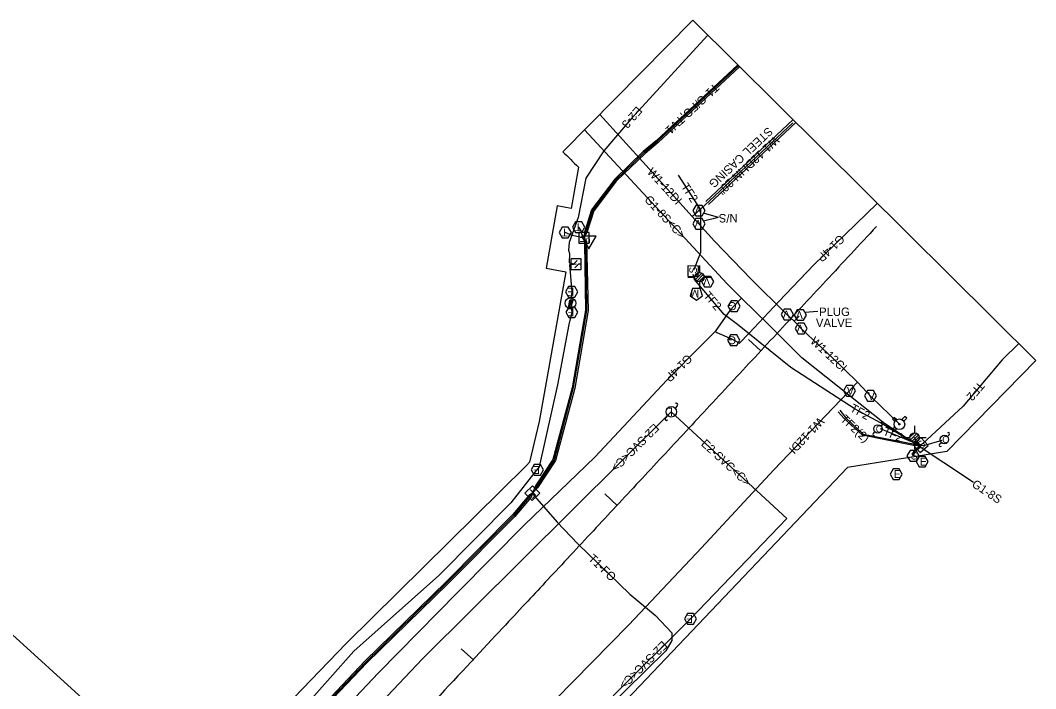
# Model space of a CAD drawing. Extents: x 1991878 to 2008544, y 770238 to 1141211.
# Drawn here: x 2008062.6 to 2008543.9, y 1139565.6 to 1139882.4 of the extents above; entities that cross this region are included whole.
import ezdxf

# ---------------------------------------------------------------- set-up
doc = ezdxf.new("R2010")
doc.units = 0
for name, color, linetype in [('RD_EX_SU_Elec', 7, 'Continuous'), ('RD_EX_SU_Gas', 7, 'Continuous'), ('RD_EX_SU_H2O', 7, 'Continuous'), ('RD_EX_SU_Misc', 7, 'Continuous'), ('RD_EX_SU_Pole', 7, 'Continuous'), ('RD_EX_SU_SwpLmt', 7, 'Continuous'), ('RD_EX_SU_Telecom', 7, 'Continuous'), ('RD_EX_SU_Trfc', 7, 'Continuous'), ('RD_EX_SU_TX_Elec', 7, 'Continuous'), ('RD_EX_SU_TX_Gas', 7, 'Continuous'), ('RD_EX_SU_TX_H2O', 7, 'Continuous'), ('RD_EX_SU_TX_Telecom', 7, 'Continuous'), ('RD_EX_SU_TX_Trfc', 7, 'Continuous'), ('RD_HC_Cl', 7, 'Continuous')]:
    doc.layers.add(name, color=color, linetype=linetype)

msp = doc.modelspace()

# ---------------------------------------------------------------- linework, layer by layer
at = {"layer": 'RD_EX_SU_Elec'}
for points in [[(2008388.37, 1139875.24), (2008352.25, 1139835.77), (2008339.19, 1139820.6), (2008330.64, 1139807.57), (2008327.03, 1139789.02), (2008322.82, 1139777.14), (2008322.44, 1139773.5), (2008322.92, 1139771.93), (2008322.8, 1139767.45), (2008326.05, 1139766.84), (2008322.91, 1139766.44), (2008324, 1139753.73), (2008323.4, 1139748.33), (2008324.09, 1139744.01), (2008322.62, 1139738.22), (2008317.2, 1139709.57), (2008308.6, 1139670.8), (2008306.52, 1139668.26), (2008295.15, 1139653.67), (2008261.07, 1139619.29), (2008220.69, 1139583.46), (2008187.13, 1139545.5)], [(2008323.55, 1139766.84), (2008324.89, 1139766.84), (2008326.58, 1139768.52)], [(2008328.55, 1139766.84), (2008327.22, 1139766.84), (2008325.53, 1139765.15)], [(2008343.6, 1139562.26), (2008380.32, 1139598.68), (2008425.97, 1139646.35), (2008371.23, 1139696.87), (2008253.32, 1139579.8), (2008186.59, 1139509.23), (2008114.35, 1139431), (2008055.21, 1139358.58), (2007994.21, 1139276.04), (2007935.15, 1139188.81), (2007828.1, 1139009.37), (2007792.89, 1138934.82)]]:
    msp.add_lwpolyline(points, dxfattribs=at)
for points in [[(2008328.55, 1139769.33), (2008323.55, 1139769.33), (2008323.55, 1139764.34), (2008328.55, 1139764.34)], [(2008321.12, 1139753.73), (2008322.56, 1139751.23), (2008325.45, 1139751.23), (2008326.89, 1139753.73), (2008325.45, 1139756.23), (2008322.56, 1139756.23)], [(2008321.21, 1139744.01), (2008322.65, 1139741.51), (2008325.54, 1139741.51), (2008326.98, 1139744.01), (2008325.54, 1139746.51), (2008322.65, 1139746.51)], [(2008324.78, 1139750.39), (2008323.78, 1139746.94), (2008323.28, 1139748.81), (2008322.51, 1139745.98), (2008323.2, 1139749.89), (2008323.76, 1139747.95)], [(2008493.04, 1139673.22), (2008491.59, 1139675.72), (2008488.71, 1139675.72), (2008487.26, 1139673.22), (2008488.71, 1139670.72), (2008491.59, 1139670.72)], [(2008304.82, 1139669.29), (2008306.27, 1139666.79), (2008309.15, 1139666.79), (2008310.6, 1139669.29), (2008309.15, 1139671.79), (2008306.27, 1139671.79)], [(2008480.67, 1139667.33), (2008479.23, 1139669.83), (2008476.34, 1139669.83), (2008474.9, 1139667.33), (2008476.34, 1139664.83), (2008479.23, 1139664.83)], [(2008377.44, 1139598.68), (2008378.88, 1139596.18), (2008381.77, 1139596.18), (2008383.21, 1139598.68), (2008381.77, 1139601.18), (2008378.88, 1139601.18)]]:
    msp.add_lwpolyline(points, close=True, dxfattribs=at)
msp.add_circle((2008323.4, 1139748.33), 2.55, dxfattribs=at)
at = {"layer": 'RD_EX_SU_Gas'}
for points in [[(2008397.47, 1139757.64), (2008351.82, 1139807.01), (2008330.11, 1139830.48)], [(2008392.07, 1139735.01), (2008392.85, 1139734.47), (2008399.7, 1139731.43), (2008403.52, 1139729.38), (2008407.96, 1139734.03), (2008422.17, 1139749.08), (2008438.65, 1139766.33), (2008468.86, 1139795.64)], [(2008514.51, 1139663.35), (2008472.32, 1139691.37), (2008433.03, 1139722.41), (2008417.25, 1139738.18), (2008404.63, 1139750.62), (2008397.47, 1139757.64)], [(2008404.55, 1139750.7), (2008403.44, 1139749.58), (2008398.9, 1139744.83), (2008391.94, 1139734.83), (2008385.92, 1139728.82), (2008369.04, 1139711.9), (2008334.96, 1139675.4), (2008301.61, 1139643.32), (2008270.11, 1139611.37), (2008232.47, 1139573.05), (2008197.32, 1139535.98), (2008163.44, 1139498.28), (2008127.84, 1139456.99), (2008097.18, 1139422.1), (2008075.86, 1139397.4), (2008030.23, 1139340.85), (2007999.81, 1139301.13), (2007969.65, 1139260.73)]]:
    msp.add_lwpolyline(points, dxfattribs=at)
for points in [[(2008399.53, 1139749.43), (2008398.08, 1139746.93), (2008399.53, 1139744.43), (2008402.41, 1139744.43), (2008403.86, 1139746.93), (2008402.41, 1139749.43)], [(2008399.32, 1139733.26), (2008397.88, 1139730.76), (2008399.32, 1139728.26), (2008402.21, 1139728.26), (2008403.65, 1139730.76), (2008402.21, 1139733.26)]]:
    msp.add_lwpolyline(points, close=True, dxfattribs=at)
at = {"layer": 'RD_EX_SU_H2O'}
for p, q in [((2008387.52, 1139796.54), (2008428.89, 1139835.31)), ((2008388.89, 1139795.08), (2008430.31, 1139833.9)), ((2008476.87, 1139694.22), (2008476, 1139693.31)), ((2008476, 1139693.31), (2008477.16, 1139692.2)), ((2008478.05, 1139693.09), (2008476.87, 1139694.22)), ((2008481.88, 1139694.63), (2008480.48, 1139693.16)), ((2008481.42, 1139692.33), (2008482.79, 1139693.76)), ((2008482.79, 1139693.76), (2008481.88, 1139694.63)), ((2008477.14, 1139689.67), (2008475.79, 1139688.25)), ((2008475.79, 1139688.25), (2008476.7, 1139687.38)), ((2008476.7, 1139687.38), (2008478.02, 1139688.77))]:
    msp.add_line(p, q, dxfattribs=at)
for points in [[(2008337.32, 1139837.77), (2008359.09, 1139813.73), (2008381.12, 1139789.42), (2008391.73, 1139777.78), (2008409.08, 1139759.67), (2008425.74, 1139743.36), (2008429.49, 1139739.79), (2008433.69, 1139735.42), (2008447.28, 1139722.79), (2008459.45, 1139710.87)], [(2008428.85, 1139833.88), (2008389.35, 1139796.85), (2008381.53, 1139789.75), (2008381.14, 1139789.39)], [(2008429.51, 1139739.77), (2008429.85, 1139740.13), (2008431.9, 1139742.18)], [(2008019.12, 1139221.08), (2008048.48, 1139262.65), (2008073.58, 1139294.58), (2008079.22, 1139302.23), (2008110.71, 1139341.71), (2008143.34, 1139380.24), (2008168.92, 1139408.5), (2008210.81, 1139454.91), (2008245.96, 1139491.17), (2008281.21, 1139525.55), (2008316.14, 1139560.25), (2008351.07, 1139595.92), (2008385.58, 1139632.4), (2008419.77, 1139669.26), (2008455.08, 1139706.22), (2008458.85, 1139710.23), (2008459.45, 1139710.87)], [(2008459.45, 1139710.87), (2008466.13, 1139703.84), (2008478.9, 1139691.52), (2008479.33, 1139690.92)]]:
    msp.add_lwpolyline(points, dxfattribs=at)
for points in [[(2008381.47, 1139792.2), (2008382.92, 1139789.7), (2008385.8, 1139789.7), (2008387.25, 1139792.2), (2008385.8, 1139794.7), (2008382.92, 1139794.7)], [(2008381.47, 1139785.9), (2008382.92, 1139783.4), (2008385.8, 1139783.4), (2008387.25, 1139785.9), (2008385.8, 1139788.4), (2008382.92, 1139788.4)], [(2008385.56, 1139758.55), (2008387.01, 1139756.05), (2008389.89, 1139756.05), (2008391.34, 1139758.55), (2008389.89, 1139761.05), (2008387.01, 1139761.05)], [(2008383.09, 1139749.73), (2008386, 1139751.84), (2008384.89, 1139755.25), (2008381.3, 1139755.25), (2008380.19, 1139751.84)], [(2008423.33, 1139742.93), (2008424.77, 1139740.43), (2008427.66, 1139740.43), (2008429.1, 1139742.93), (2008427.66, 1139745.43), (2008424.77, 1139745.43)], [(2008429.49, 1139742.71), (2008430.93, 1139740.21), (2008433.82, 1139740.21), (2008435.26, 1139742.71), (2008433.82, 1139745.21), (2008430.93, 1139745.21)], [(2008429.86, 1139736.31), (2008431.3, 1139733.81), (2008434.19, 1139733.81), (2008435.63, 1139736.31), (2008434.19, 1139738.81), (2008431.3, 1139738.81)], [(2008458.54, 1139706.79), (2008457.1, 1139709.29), (2008454.21, 1139709.29), (2008452.77, 1139706.79), (2008454.21, 1139704.29), (2008457.1, 1139704.29)], [(2008468.53, 1139704.37), (2008467.09, 1139706.87), (2008464.2, 1139706.87), (2008462.76, 1139704.37), (2008464.2, 1139701.87), (2008467.09, 1139701.87)]]:
    msp.add_lwpolyline(points, close=True, dxfattribs=at)
for radius in [2.52, 0.315]:
    msp.add_circle((2008479.33, 1139690.92), radius, dxfattribs=at)
for start, end in [(120.5537, 149.521), (33.9932, 62.9695), (209.6469, 238.6232)]:
    msp.add_arc((2008479.33, 1139690.92), 2.52, start, end, dxfattribs=at)
at = {"layer": 'RD_EX_SU_Misc'}
msp.add_lwpolyline([(2008332.18, 1139774.11), (2008335.65, 1139780.11), (2008328.72, 1139780.11)], close=True, dxfattribs=at)
at = {"layer": 'RD_EX_SU_Pole'}
for p, q in [((2008384.59, 1139766.12), (2008384.59, 1139762.83)), ((2008379.06, 1139760.61), (2008382.37, 1139760.61)), ((2008382.37, 1139760.75), (2008384.45, 1139762.83)), ((2008382.62, 1139759.58), (2008385.62, 1139762.58)), ((2008383.28, 1139758.83), (2008386.38, 1139761.92)), ((2008384.29, 1139758.42), (2008386.78, 1139760.91)), ((2008386.8, 1139760.62), (2008390.11, 1139760.62)), ((2008384.59, 1139758.4), (2008384.59, 1139755.12)), ((2008374.06, 1139699.7), (2008373, 1139698.64)), ((2008369.47, 1139695.11), (2008368.41, 1139694.04)), ((2008486.55, 1139690.12), (2008486.55, 1139686.84)), ((2008481.03, 1139684.61), (2008484.34, 1139684.62)), ((2008484.34, 1139684.75), (2008486.42, 1139686.83)), ((2008484.59, 1139683.59), (2008487.59, 1139686.58)), ((2008485.25, 1139682.83), (2008488.34, 1139685.93)), ((2008486.26, 1139682.42), (2008488.75, 1139684.92)), ((2008488.77, 1139684.62), (2008492.08, 1139684.63)), ((2008486.55, 1139682.4), (2008486.55, 1139679.12))]:
    msp.add_line(p, q, dxfattribs=at)
for centre, radius in [((2008384.59, 1139760.62), 2.22), ((2008371.23, 1139696.87), 2.5), ((2008486.55, 1139684.62), 2.22)]:
    msp.add_circle(centre, radius, dxfattribs=at)
for centre, start, end in [((2008373.53, 1139700.23), 315, 135), ((2008368.94, 1139693.51), 135, 315)]:
    msp.add_arc(centre, 0.75, start, end, dxfattribs=at)
at = {"layer": 'RD_EX_SU_SwpLmt'}
for p, q in [((2008381.44, 1139882.41), (2008319.85, 1139820.11)), ((2008381.44, 1139882.41), (2008543.95, 1139721.11)), ((2008327.21, 1139812.76), (2008323.75, 1139793.27)), ((2008321.23, 1139763.24), (2008308.62, 1139692.22)), ((2008543.95, 1139721.11), (2008501.79, 1139678.03))]:
    msp.add_line(p, q, dxfattribs=at)
for points in [[(2008323.75, 1139793.27), (2008317.17, 1139794.43), (2008311.92, 1139764.9), (2008321.23, 1139763.24)], [(2008308.62, 1139692.22), (2008303.98, 1139673.05), (2008302.61, 1139671.39), (2008217.14, 1139586.99), (2008146.65, 1139513.91), (2008110.85, 1139472.17), (2008058.97, 1139410.99), (2008013.6, 1139356.01), (2007982.19, 1139312.98), (2007954.73, 1139272.11), (2007894.74, 1139182.48), (2007866.63, 1139138.23), (2007843.93, 1139094.78), (2007785.35, 1138986.79)], [(2008501.79, 1139678.03), (2008454.81, 1139670.38), (2008273.17, 1139479.53)]]:
    msp.add_lwpolyline(points, dxfattribs=at)
msp.add_arc((2022509.04, 1154031.15), 20082, 225.044092, 225.073753, dxfattribs=at)
at = {"layer": 'RD_EX_SU_Telecom'}
for points in [[(2008403.08, 1139860.82), (2008364.54, 1139824.89), (2008358.29, 1139819.76), (2008344.82, 1139806.68), (2008333.88, 1139792.27), (2008330.57, 1139781.92), (2008329.82, 1139779.33), (2008330.66, 1139775.7), (2008331.1, 1139744.9), (2008324.72, 1139708.32), (2008315.66, 1139674.01), (2008307.42, 1139661.37), (2008305.4, 1139658.27)], [(2008402.66, 1139861.19), (2008364.05, 1139825.29), (2008357.91, 1139820.18), (2008344.46, 1139807.16), (2008333.36, 1139792.52), (2008330, 1139782.02), (2008329.82, 1139779.33)], [(2008403.49, 1139860.33), (2008364.93, 1139824.55), (2008358.82, 1139819.34), (2008345.16, 1139806.09), (2008334.42, 1139792.1), (2008331.21, 1139781.85), (2008329.82, 1139779.33)], [(2008329.82, 1139779.33), (2008328.05, 1139779.7), (2008324.26, 1139780.46), (2008320.96, 1139781.85)], [(2008329.82, 1139779.33), (2008328.95, 1139780.8), (2008328.38, 1139782.96), (2008327.32, 1139784.36)], [(2008329.82, 1139779.33), (2008330, 1139776.71), (2008330.54, 1139745.03), (2008324.17, 1139708.28), (2008315.14, 1139674.26), (2008306.86, 1139661.74), (2008305.4, 1139658.27)], [(2008329.82, 1139779.33), (2008331.06, 1139777.44), (2008331.79, 1139744.88), (2008325.48, 1139708.06), (2008316.32, 1139673.77), (2008307.85, 1139660.86), (2008305.4, 1139658.27)], [(2008305.4, 1139658.27), (2008303.69, 1139657.15), (2008296.15, 1139648.2), (2008264.57, 1139616.22), (2008225.94, 1139578.68), (2008191.19, 1139541.83), (2008155.65, 1139504.96), (2008121.25, 1139463.29), (2008090.5, 1139429.06), (2008067.62, 1139404.3), (2008020.3, 1139350.24), (2008000.26, 1139321.01), (2007991.22, 1139306.98), (2007963.62, 1139266.78), (2007931.75, 1139219.86)], [(2008305.4, 1139658.27), (2008304.18, 1139656.84), (2008296.58, 1139647.74), (2008264.95, 1139615.87), (2008226.45, 1139578.22), (2008191.55, 1139541.46), (2008156.07, 1139504.61), (2008121.74, 1139462.81), (2008090.98, 1139428.65), (2008068.11, 1139403.96), (2008020.75, 1139349.83), (2008000.71, 1139320.77), (2007991.64, 1139306.71), (2007964.15, 1139266.38), (2007932.21, 1139219.57)], [(2008305.4, 1139658.27), (2008304.81, 1139656.42), (2008297.07, 1139647.18), (2008265.35, 1139615.32), (2008226.85, 1139577.83), (2008191.88, 1139541.09), (2008156.34, 1139504.22), (2008122.19, 1139462.43), (2008091.39, 1139428.14), (2008068.51, 1139403.49), (2008021.17, 1139349.41), (2008001.14, 1139320.51), (2007992.13, 1139306.45), (2007964.8, 1139266.15), (2007932.81, 1139219.12)], [(2008305.4, 1139658.27), (2008306.31, 1139656.83), (2008317.12, 1139644.5), (2008326.86, 1139634.24), (2008351.55, 1139610.4), (2008363.7, 1139600.31), (2008371.53, 1139592.02), (2008371.51, 1139588.49), (2008368.63, 1139583.51), (2008330.84, 1139546.49), (2008295.07, 1139510.2), (2008260.86, 1139475.1), (2008227.88, 1139441.1), (2008205.45, 1139415.71), (2008205.11, 1139411.02), (2008208.34, 1139399.62), (2008209.03, 1139398.46)]]:
    msp.add_lwpolyline(points, dxfattribs=at)
for points in [[(2008324.44, 1139784.36), (2008325.88, 1139781.86), (2008328.77, 1139781.86), (2008330.21, 1139784.36), (2008328.77, 1139786.86), (2008325.88, 1139786.86)], [(2008318.07, 1139781.85), (2008319.51, 1139779.35), (2008322.4, 1139779.35), (2008323.84, 1139781.85), (2008322.4, 1139784.35), (2008319.51, 1139784.35)], [(2008327.32, 1139776.83), (2008332.32, 1139776.83), (2008332.32, 1139781.83), (2008327.32, 1139781.83)], [(2008305.33, 1139654.74), (2008308.94, 1139658.21), (2008305.47, 1139661.81), (2008301.87, 1139658.34)]]:
    msp.add_lwpolyline(points, close=True, dxfattribs=at)
at = {"layer": 'RD_EX_SU_Trfc'}
for p, q in [((2008470.59, 1139690.14), (2008471.44, 1139690.99)), ((2008466.91, 1139686.46), (2008467.76, 1139687.31)), ((2008502.1, 1139685.12), (2008502.95, 1139685.97)), ((2008498.42, 1139681.45), (2008499.27, 1139682.29))]:
    msp.add_line(p, q, dxfattribs=at)
for points in [[(2008382.05, 1139764.31), (2008385.25, 1139772.57), (2008385.21, 1139792.54), (2008374.63, 1139808.94)], [(2008489.37, 1139681.06), (2008487.54, 1139682.05), (2008484.83, 1139683), (2008470.36, 1139691.62), (2008458.3, 1139698.15), (2008427.87, 1139717.83), (2008402.63, 1139738.28), (2008396.35, 1139742.96), (2008382.19, 1139759.54), (2008381.54, 1139762.01)], [(2008535.96, 1139729.15), (2008528.12, 1139721.48), (2008509.49, 1139699.52), (2008490.35, 1139681.7), (2008489.37, 1139681.06)], [(2008489.37, 1139681.06), (2008487.8, 1139680.76), (2008485.3, 1139681), (2008461.8, 1139685.72), (2008453.15, 1139693.74), (2008450.27, 1139696.87)], [(2008451.08, 1139697.58), (2008453.86, 1139694.17), (2008462.14, 1139686.22), (2008487.43, 1139681.33), (2008489.37, 1139681.06)], [(2008489.37, 1139681.06), (2008487.43, 1139681.67), (2008470.35, 1139688.72)], [(2008489.37, 1139681.06), (2008488.5, 1139681.86), (2008487.52, 1139682.81), (2008486.55, 1139684.62)], [(2008489.37, 1139681.06), (2008490.96, 1139680.91), (2008499.58, 1139683.38)], [(2008489.37, 1139681.06), (2008489.16, 1139679.85), (2008486.68, 1139677.85), (2008485.83, 1139676)], [(2008485.83, 1139676), (2008486.16, 1139678.42), (2008488.42, 1139680.31), (2008489.37, 1139681.06)]]:
    msp.add_lwpolyline(points, dxfattribs=at)
for points in [[(2008379.12, 1139766.06), (2008378.99, 1139761.06), (2008383.98, 1139760.93), (2008384.12, 1139765.92)], [(2008489.49, 1139684.6), (2008485.84, 1139681.19), (2008489.24, 1139677.53), (2008492.9, 1139680.94)], [(2008488.71, 1139676), (2008487.27, 1139678.5), (2008484.38, 1139678.5), (2008482.94, 1139676), (2008484.38, 1139673.5), (2008487.27, 1139673.5)]]:
    msp.add_lwpolyline(points, close=True, dxfattribs=at)
for centre in [(2008469.17, 1139688.72), (2008500.68, 1139683.71)]:
    msp.add_circle(centre, 2, dxfattribs=at)
for centre, start, end in [((2008471.01, 1139691.41), 315, 135), ((2008467.33, 1139686.04), 135, 315), ((2008502.52, 1139686.4), 315, 135), ((2008498.85, 1139681.02), 135, 315)]:
    msp.add_arc(centre, 0.6, start, end, dxfattribs=at)
at = {"layer": 'RD_EX_SU_TX_H2O'}
for p, q in [((2008393.66, 1139788.89), (2008386.53, 1139790.95)), ((2008393.66, 1139788.89), (2008386.53, 1139787.15)), ((2008440.63, 1139744.36), (2008434.54, 1139743.96))]:
    msp.add_line(p, q, dxfattribs=at)
at = {"layer": 'RD_HC_Cl'}
for p, q in [((2008407.76, 1139731.14), (2008413.62, 1139725.69)), ((2007960.14, 1139680.51), (2008408.6, 1139274.45)), ((2008339.66, 1139657.9), (2008345.53, 1139652.46)), ((2008271.66, 1139584.56), (2008277.54, 1139579.13))]:
    msp.add_line(p, q, dxfattribs=at)
msp.add_open_spline([(2008468.44, 1139784.65), (2008330.54, 1139636.27), (2008112.04, 1139402.61), (2008010.65, 1139269.99), (2007954.96, 1139181.47), (2007845.36, 1139006.33), (2007807.05, 1138915.36), (2007714.1, 1138721), (2007657.93, 1138535.69), (2007584.82, 1138278.81), (2007557.24, 1138105.93), (2007524.47, 1137887.62), (2007511.86, 1137606.6), (2007518.19, 1137380.97), (2007535.52, 1137158.14), (2007573, 1136960.76), (2007648.83, 1136694.4), (2007817.41, 1136298.79), (2008044.24, 1135795.68), (2008373.08, 1135014.28)], degree=2, dxfattribs=at)

# ---------------------------------------------------------------- texts
at = {"layer": 'RD_EX_SU_Elec'}
for rotation, p in [(180, (2008325.14, 1139755.61)), (180, (2008325.23, 1139745.89)), (180, (2008308.85, 1139671.16)), (360, (2008476.65, 1139665.46)), (180, (2008381.46, 1139600.56))]:
    msp.add_text('E', height=3.75, rotation=rotation, dxfattribs=at).set_placement(p)
msp.add_text('E', height=3.75, dxfattribs=at).set_placement((2008489.01, 1139671.35))
at = {"layer": 'RD_EX_SU_Gas'}
for p in [(2008402.12, 1139748.81), (2008401.92, 1139732.63)]:
    msp.add_text('G', height=3.75, rotation=180, dxfattribs=at).set_placement(p)
at = {"layer": 'RD_EX_SU_H2O'}
for s, p in [('V', (2008385.57, 1139794.07)), ('V', (2008385.57, 1139787.77)), ('V', (2008389.66, 1139760.42)), ('M', (2008384.46, 1139754.77)), ('V', (2008427.42, 1139744.81)), ('V', (2008433.59, 1139744.58)), ('V', (2008433.95, 1139738.18))]:
    msp.add_text(s, height=3.75, rotation=180, dxfattribs=at).set_placement(p)
for p in [(2008454.45, 1139704.91), (2008464.43, 1139702.5)]:
    msp.add_text('V', height=3.75, dxfattribs=at).set_placement(p)
at = {"layer": 'RD_EX_SU_Misc'}
msp.add_text('U', height=2.4, rotation=180, dxfattribs=at).set_placement((2008332.94, 1139779.31))
at = {"layer": 'RD_EX_SU_Pole'}
msp.add_text('L', height=4, rotation=180, dxfattribs=at).set_placement((2008372.04, 1139698.81))
at = {"layer": 'RD_EX_SU_Telecom'}
for s, height, rotation, p in [('T', 3.75, 180, (2008328.53, 1139786.24)), ('T', 3.75, 180, (2008322.17, 1139783.72)), ('F', 4, 180, (2008330.95, 1139781.33)), ('F', 4, 223.8869, (2008304.83, 1139660.5))]:
    msp.add_text(s, height=height, rotation=rotation, dxfattribs=at).set_placement(p)
at = {"layer": 'RD_EX_SU_Trfc'}
for rotation, p in [(88.417, (2008383.29, 1139762.36)), (42.9469, (2008489.78, 1139679.03))]:
    msp.add_text('S', height=3.53, rotation=rotation, dxfattribs=at).set_placement(p)
for s, height, p in [('O', 3.2, (2008468.14, 1139687.12)), ('O', 3.2, (2008499.65, 1139682.11)), ('S', 3.53, (2008484.74, 1139674.23))]:
    msp.add_text(s, height=height, dxfattribs=at).set_placement(p)
at = {"layer": 'RD_EX_SU_TX_Elec'}
for s, rotation, p in [('E2-3', 229.2867, (2008354.77, 1139841.95)), ('E2-SVC<C>', 224.7946, (2008363.06, 1139691.57)), ('E2-SVC<C>', 317.2899, (2008385.01, 1139681.25)), ('E2-SVC<C>', 224.765, (2008366.96, 1139588.55))]:
    msp.add_text(s, height=4, rotation=rotation, dxfattribs=at).set_placement(p)
at = {"layer": 'RD_EX_SU_TX_Gas'}
for s, rotation, p in [('G1-8S<C>', 312.76, (2008358.2, 1139797.16)), ('G1-4P', 224.1371, (2008451.05, 1139781.14)), ('G1-4P', 225.0739, (2008378.72, 1139724.43)), ('G1-8S', 326.4163, (2008513.31, 1139661.63))]:
    msp.add_text(s, height=4, rotation=rotation, dxfattribs=at).set_placement(p)
at = {"layer": 'RD_EX_SU_TX_H2O'}
for s, rotation, p in [('STEEL CASING', 223.1552, (2008417.04, 1139832.1)), ('W1-12DI IN 20"', 223.1552, (2008420.04, 1139827.77)), ('W1-12DI', 312.171, (2008359.5, 1139810.3)), ('N/S', 180.0098, (2008402.67, 1139790.59)), ('PLUG', 0.0098, (2008441.27, 1139742.25)), ('VALVE', 0.0098, (2008439.77, 1139737.04)), ('W1-12CI', 317.1022, (2008436.77, 1139729.83)), ('W1-12DI', 226.3082, (2008441.16, 1139694.54))]:
    msp.add_text(s, height=4, rotation=rotation, dxfattribs=at).set_placement(p)
at = {"layer": 'RD_EX_SU_TX_Telecom'}
for s, rotation, p in [('T1-C/FO,TV1', 222.9947, (2008391.58, 1139852.84)), ('T1-FO', 315.9923, (2008331.6, 1139626.89))]:
    msp.add_text(s, height=4, rotation=rotation, dxfattribs=at).set_placement(p)
at = {"layer": 'RD_EX_SU_TX_Trfc'}
for s, rotation, p in [('TF2', 302.8387, (2008375.66, 1139803.65)), ('TF2', 310.4835, (2008386.22, 1139751.74)), ('TF2', 229.6962, (2008517.01, 1139711.47)), ('TF2', 331.5652, (2008455.61, 1139697.33)), ('TF2(2)', 317.1619, (2008451.14, 1139692.87)), ('TF2', 337.5771, (2008471.24, 1139686.08))]:
    msp.add_text(s, height=4, rotation=rotation, dxfattribs=at).set_placement(p)

doc.saveas('drawing.dxf')
